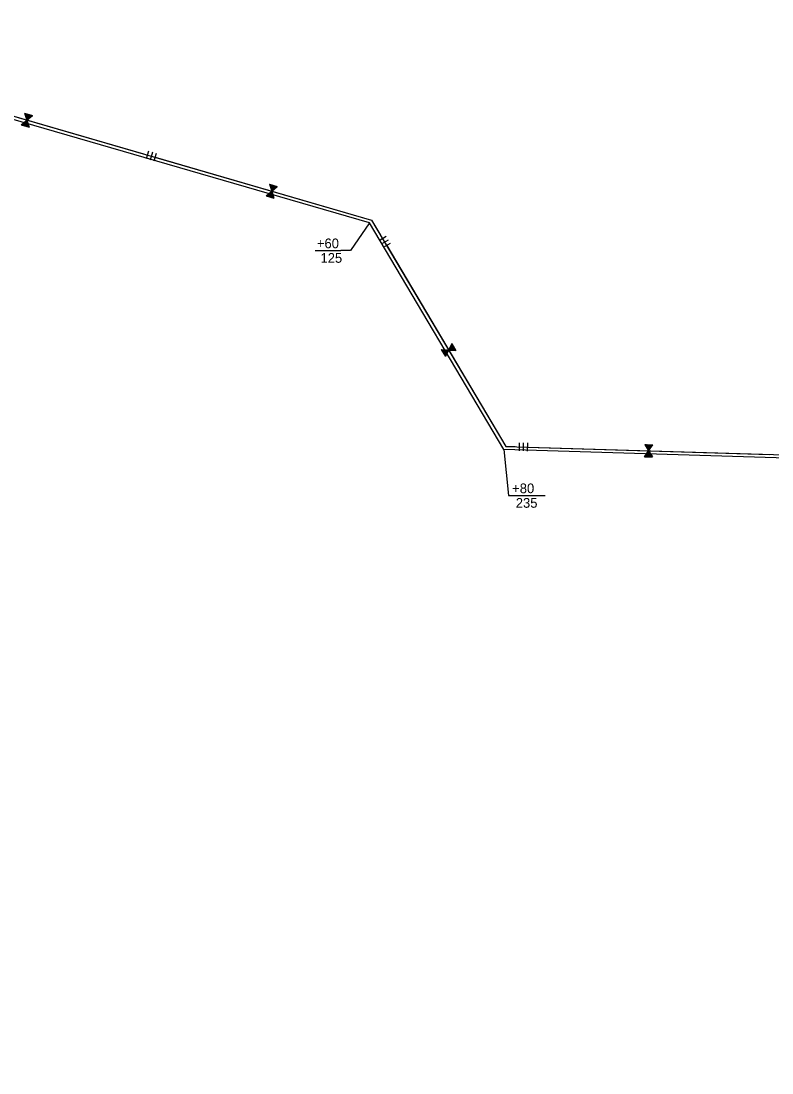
# Model space of a CAD drawing. Extents: x 979729 to 993523, y 1834148 to 1845433.
# Drawn here: x 981898 to 982362, y 1837610 to 1838260 of the extents above; entities that cross this region are included whole.
import ezdxf

# ---------------------------------------------------------------- set-up
doc = ezdxf.new("R2010")
doc.units = 0
for name, color, linetype in [('42', 7, 'Continuous'), ('51', 7, 'Continuous'), ('R_Draft', 7, 'Continuous')]:
    doc.layers.add(name, color=color, linetype=linetype)

msp = doc.modelspace()

# ---------------------------------------------------------------- linework, layer by layer
at = {"layer": '42'}
for p, q in [((981690.99, 1838260.28), (982114.9, 1838137.28)), ((981900.61, 1838203.36), (981901.96, 1838199.07)), ((981900.65, 1838203.3), (981900.7, 1838203.34)), ((981900.75, 1838203.05), (981900.99, 1838203.25)), ((981900.81, 1838202.78), (981901.27, 1838203.17)), ((981900.91, 1838202.53), (981901.56, 1838203.09)), ((981900.97, 1838202.26), (981901.85, 1838203)), ((981901.04, 1838201.99), (981902.14, 1838202.92)), ((981901.14, 1838201.75), (981902.43, 1838202.84)), ((981901.28, 1838201.54), (981902.59, 1838202.65)), ((981901.32, 1838201.25), (981903.01, 1838202.67)), ((981901.42, 1838201), (981903.3, 1838202.58)), ((981901.46, 1838200.71), (981903.58, 1838202.5)), ((981901.58, 1838200.49), (981903.87, 1838202.42)), ((981901.63, 1838200.2), (981904.16, 1838202.33)), ((981901.72, 1838199.95), (981904.45, 1838202.25)), ((981901.79, 1838199.68), (981904.74, 1838202.17)), ((981901.91, 1838199.45), (981905.03, 1838202.08)), ((981901.95, 1838199.17), (981905.31, 1838202)), ((981901.96, 1838199.07), (981905.41, 1838201.97)), ((981898.52, 1838196.16), (981901.96, 1838199.07)), ((981898.59, 1838196.2), (981898.61, 1838196.14)), ((981898.8, 1838196.35), (981898.9, 1838196.05)), ((981899, 1838196.55), (981899.18, 1838195.97)), ((981899.22, 1838196.7), (981899.47, 1838195.88)), ((981899.42, 1838196.9), (981899.76, 1838195.8)), ((981899.62, 1838197.09), (981900.05, 1838195.72)), ((981899.83, 1838197.24), (981900.34, 1838195.63)), ((981900.06, 1838197.34), (981900.58, 1838195.71)), ((981900.25, 1838197.57), (981900.92, 1838195.47)), ((981900.47, 1838197.72), (981901.21, 1838195.38)), ((981900.66, 1838197.94), (981901.49, 1838195.3)), ((981900.88, 1838198.07), (981901.78, 1838195.21)), ((981901.07, 1838198.29), (981902.07, 1838195.13)), ((981901.29, 1838198.45), (981902.36, 1838195.05)), ((981901.49, 1838198.64), (981902.65, 1838194.96)), ((981901.71, 1838198.77), (981902.94, 1838194.88)), ((981901.9, 1838198.99), (981903.22, 1838194.8)), ((981901.96, 1838199.07), (981903.32, 1838194.77)), ((981977.09, 1838179.87), (981975.7, 1838175.07)), ((981979.49, 1838179.17), (981978.1, 1838174.37)), ((981981.89, 1838178.48), (981980.5, 1838173.67)), ((982051.87, 1838159.47), (982053.23, 1838155.17)), ((982051.91, 1838159.41), (982051.96, 1838159.45)), ((982052.01, 1838159.16), (982052.25, 1838159.36)), ((982052.07, 1838158.89), (982052.54, 1838159.28)), ((982052.17, 1838158.64), (982052.82, 1838159.2)), ((982052.24, 1838158.37), (982053.11, 1838159.11)), ((982052.3, 1838158.1), (982053.4, 1838159.03)), ((982052.4, 1838157.86), (982053.69, 1838158.94)), ((982052.54, 1838157.65), (982053.85, 1838158.75)), ((982052.58, 1838157.36), (982054.27, 1838158.78)), ((982052.68, 1838157.11), (982054.56, 1838158.69)), ((982052.72, 1838156.82), (982054.84, 1838158.61)), ((982052.84, 1838156.6), (982055.13, 1838158.53)), ((982052.89, 1838156.31), (982055.42, 1838158.44)), ((982052.99, 1838156.06), (982055.71, 1838158.36)), ((982053.05, 1838155.79), (982056, 1838158.27)), ((982053.17, 1838155.56), (982056.29, 1838158.19)), ((982053.21, 1838155.27), (982056.58, 1838158.11)), ((982053.23, 1838155.17), (982056.67, 1838158.08)), ((982049.78, 1838152.27), (982053.23, 1838155.17)), ((982049.85, 1838152.31), (982049.87, 1838152.24)), ((982050.06, 1838152.46), (982050.16, 1838152.16)), ((982050.26, 1838152.66), (982050.45, 1838152.08)), ((982050.48, 1838152.81), (982050.73, 1838151.99)), ((982050.68, 1838153), (982051.02, 1838151.91)), ((982050.88, 1838153.2), (982051.31, 1838151.83)), ((982051.09, 1838153.35), (982051.6, 1838151.74)), ((982051.32, 1838153.45), (982051.84, 1838151.82)), ((982051.51, 1838153.68), (982052.18, 1838151.57)), ((982051.73, 1838153.83), (982052.47, 1838151.49)), ((982051.92, 1838154.05), (982052.75, 1838151.41)), ((982052.14, 1838154.18), (982053.04, 1838151.32)), ((982052.33, 1838154.4), (982053.33, 1838151.24)), ((982052.55, 1838154.55), (982053.62, 1838151.16)), ((982052.75, 1838154.75), (982053.91, 1838151.07)), ((982052.97, 1838154.88), (982054.2, 1838150.99)), ((982053.16, 1838155.1), (982054.49, 1838150.9)), ((982053.23, 1838155.17), (982054.58, 1838150.88)), ((982114.9, 1838137.28), (982197.75, 1837997.51)), ((982123.82, 1838127.13), (982119.52, 1838124.58)), ((982125.1, 1838124.98), (982120.8, 1838122.43)), ((982126.37, 1838122.83), (982122.07, 1838120.28)), ((982164.41, 1838061.1), (982162.46, 1838057.03)), ((982162.99, 1838058.09), (982166.3, 1838057.91)), ((982163.16, 1838058.33), (982166.15, 1838058.17)), ((982163.23, 1838058.58), (982165.99, 1838058.43)), ((982163.39, 1838058.82), (982165.84, 1838058.69)), ((982163.49, 1838059.07), (982165.69, 1838058.95)), ((982163.66, 1838059.31), (982165.37, 1838059.22)), ((982163.7, 1838059.56), (982165.38, 1838059.47)), ((982163.79, 1838059.8), (982165.23, 1838059.72)), ((982163.93, 1838060.04), (982165.08, 1838059.98)), ((982164.07, 1838060.29), (982164.92, 1838060.24)), ((982164.16, 1838060.53), (982164.77, 1838060.5)), ((982164.3, 1838060.77), (982164.62, 1838060.76)), ((982164.4, 1838061.02), (982164.46, 1838061.02)), ((982157.96, 1838057.27), (982162.46, 1838057.03)), ((982158.04, 1838057.25), (982158.01, 1838057.19)), ((982158.3, 1838057.22), (982158.16, 1838056.93)), ((982158.58, 1838057.22), (982158.32, 1838056.68)), ((982158.84, 1838057.19), (982158.47, 1838056.42)), ((982159.12, 1838057.19), (982158.62, 1838056.16)), ((982159.4, 1838057.2), (982158.78, 1838055.9)), ((982159.66, 1838057.16), (982158.93, 1838055.64)), ((982159.89, 1838057.07), (982159.16, 1838055.53)), ((982160.19, 1838057.11), (982159.24, 1838055.12)), ((982160.45, 1838057.08), (982159.39, 1838054.87)), ((982160.74, 1838057.11), (982159.54, 1838054.61)), ((982160.99, 1838057.05), (982159.7, 1838054.35)), ((982161.28, 1838057.08), (982159.85, 1838054.09)), ((982161.54, 1838057.05), (982160, 1838053.83)), ((982161.82, 1838057.05), (982160.16, 1838053.57)), ((982162.07, 1838056.99), (982160.31, 1838053.32)), ((982162.37, 1838057.02), (982160.46, 1838053.06)), ((982162.46, 1838057.03), (982160.51, 1838052.97)), ((982162.46, 1838057.03), (982166.96, 1838056.8)), ((982162.52, 1838057.11), (982166.91, 1838056.88)), ((982162.69, 1838057.36), (982166.76, 1838057.14)), ((982162.76, 1838057.6), (982166.61, 1838057.4)), ((982162.9, 1838057.85), (982166.45, 1838057.66)), ((982206.12, 1837999.75), (982205.97, 1837994.75)), ((982208.62, 1837999.68), (982208.47, 1837994.68)), ((982211.12, 1837999.6), (982210.97, 1837994.6)), ((982197.75, 1837997.51), (982600.97, 1837985.09)), ((982283.39, 1837991.12), (982286.01, 1837994.79)), ((982283.63, 1837998.62), (982286.01, 1837994.79)), ((982283.68, 1837998.56), (982283.72, 1837998.61)), ((982283.84, 1837998.35), (982284.02, 1837998.6)), ((982283.97, 1837998.1), (982284.32, 1837998.59)), ((982284.12, 1837997.89), (982284.62, 1837998.59)), ((982284.25, 1837997.64), (982284.92, 1837998.58)), ((982284.39, 1837997.4), (982285.22, 1837998.57)), ((982284.54, 1837997.18), (982285.52, 1837998.56)), ((982284.73, 1837997.02), (982285.72, 1837998.41)), ((982284.84, 1837996.74), (982286.12, 1837998.54)), ((982284.89, 1837993.12), (982286.19, 1837991.03)), ((982285, 1837996.53), (982286.42, 1837998.53)), ((982285.02, 1837993.38), (982286.49, 1837991.02)), ((982285.11, 1837996.26), (982286.72, 1837998.52)), ((982285.21, 1837993.56), (982286.79, 1837991.02)), ((982285.29, 1837996.07), (982287.02, 1837998.51)), ((982285.34, 1837993.82), (982287.09, 1837991.01)), ((982285.4, 1837995.8), (982287.32, 1837998.5)), ((982285.51, 1837994.02), (982287.39, 1837991)), ((982285.56, 1837995.59), (982287.62, 1837998.49)), ((982285.65, 1837994.26), (982287.69, 1837990.99)), ((982285.69, 1837995.34), (982287.92, 1837998.48)), ((982285.84, 1837994.44), (982287.99, 1837990.98)), ((982285.86, 1837995.15), (982288.22, 1837998.47)), ((982285.97, 1837994.89), (982288.52, 1837998.47)), ((982285.97, 1837994.7), (982288.29, 1837990.97)), ((982286.01, 1837994.79), (982288.62, 1837998.46)), ((982286.01, 1837994.79), (982288.39, 1837990.97)), ((982283.45, 1837991.17), (982283.49, 1837991.12)), ((982283.62, 1837991.38), (982283.79, 1837991.11)), ((982283.77, 1837991.61), (982284.09, 1837991.1)), ((982283.94, 1837991.82), (982284.39, 1837991.09)), ((982284.08, 1837992.06), (982284.69, 1837991.08)), ((982284.23, 1837992.29), (982284.99, 1837991.07)), ((982284.4, 1837992.5), (982285.29, 1837991.06)), ((982284.6, 1837992.64), (982285.5, 1837991.19)), ((982284.73, 1837992.91), (982285.89, 1837991.04))]:
    msp.add_line(p, q, dxfattribs=at)
for points in [[(981829.94, 1838219.97), (981973.99, 1838178.17)], [(981900.61, 1838203.36), (981905.41, 1838201.97)], [(981898.52, 1838196.16), (981903.32, 1838194.77)], [(981981.2, 1838176.08), (982114.9, 1838137.28), (982120.4, 1838128)], [(982051.87, 1838159.47), (982056.67, 1838158.08)], [(982049.78, 1838152.27), (982054.58, 1838150.88)], [(982124.22, 1838121.55), (982197.75, 1837997.51), (982203.55, 1837997.33)], [(982164.41, 1838061.1), (982166.96, 1838056.8)], [(982157.96, 1838057.27), (982160.51, 1838052.97)], [(982211.04, 1837997.1), (982360.97, 1837992.48)], [(982283.63, 1837998.62), (982288.62, 1837998.46)], [(982283.39, 1837991.12), (982288.39, 1837990.97)]]:
    msp.add_lwpolyline(points, dxfattribs=at)
at = {"layer": '51'}
msp.add_lwpolyline([(983832.14, 1837610.35), (983652.57, 1837707.14), (983510.47, 1837676.41), (983408.2, 1837770.04), (983207.39, 1837710.64), (983118.6, 1837831.53), (982865.15, 1837788.06), (982600.28, 1837983.11), (982196.59, 1837995.54), (982113.58, 1838135.58), (981690.98, 1838258.2), (981584.78, 1838227.65)], dxfattribs=at)
at = {"layer": 'R_Draft'}
for p, q in [((982080.03, 1838118.41), (982095.83, 1838118.41)), ((982205.36, 1837967.06), (982222.12, 1837967.06))]:
    msp.add_line(p, q, dxfattribs=at)
for points in [[(982113.58, 1838135.58), (982101.83, 1838118.41), (982095.83, 1838118.41)], [(982196.59, 1837995.54), (982199.36, 1837967.06), (982205.36, 1837967.06)]]:
    msp.add_lwpolyline(points, dxfattribs=at)

# ---------------------------------------------------------------- texts
for s, p in [('+60', (982081.12, 1838119.91)), (' 125', (982081.12, 1838110.91)), ('+80', (982201.73, 1837968.56)), (' 235', (982201.73, 1837959.56))]:
    msp.add_text(s, height=6, rotation=360, dxfattribs=at).set_placement(p)

doc.saveas('drawing.dxf')
